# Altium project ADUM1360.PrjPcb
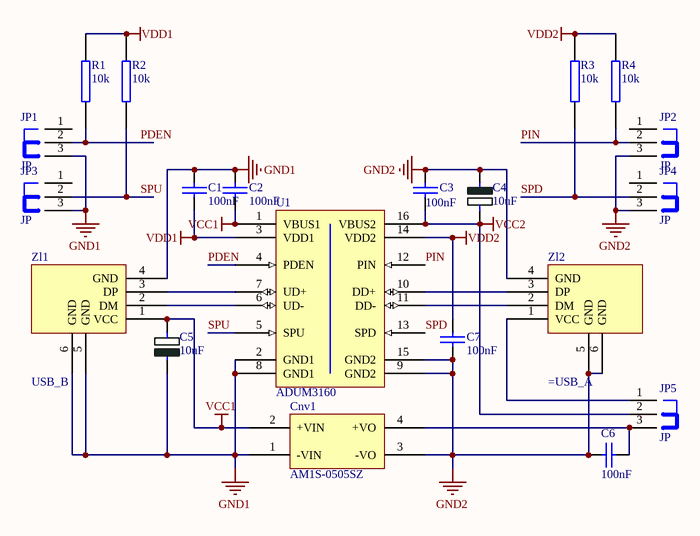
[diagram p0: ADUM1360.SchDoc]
1 sheet, 20 parts. Net scope: global (net labels, ports and power ports of the same name join across sheets).
Board file: adum1360.PcbDoc

## Sheet ADUM1360.SchDoc
size A4

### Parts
C1  100nF  [0805]
C2  100nF  [0805]
C3  100nF  [0805]
C4  10uF  [CE_SMD_W]
C5  10uF  [CE_SMD_W]
C6  100nF  [0805]
C7  100nF  [0805]
Cnv1  AM1S-0505SZ  [SIP4_AM1S]
JP1  JP  [sip-3]
JP2  JP  [sip-3]
JP3  JP  [sip-3]
JP4  JP  [sip-3]
JP5  JP  [sip-3]
R1  10k  [0805]
R2  10k  [0805]
R3  10k  [0805]
R4  10k  [0805]
U1  ADUM3160  [SOL-16]
Zl1  USB_B  [USB_B]
Zl2  (no value)  [USB_A]

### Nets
GND1: C1.1 C2.1 C5.2(MINUS) Cnv1.1(-VIN) JP1.3 JP3.3 U1.2(GND1) U1.8(GND1) Zl1.4(GND) Zl1.5(GND) Zl1.6(GND)
GND2: C3.1 C4.2(MINUS) C6.1 C7.2 Cnv1.3(-VO) JP2.3 JP4.3 U1.9(GND2) U1.15(GND2) Zl2.4(GND) Zl2.5(GND) Zl2.6(GND)
VCC1: C2.2 C5.1(PLUS) Cnv1.2(+VIN) U1.1(VBUS1) Zl1.1(VCC)
VCC2: C3.2 C4.1(PLUS) JP5.2 U1.16(VBUS2)
VDD1: C1.2 R1.2 R2.2 U1.3(VDD1)
VDD2: C7.1 R3.2 R4.2 U1.14(VDD2)
PDEN: JP1.2 R1.1 U1.4(PDEN)
PIN: JP2.2 R4.1 U1.12(PIN)
SPD: JP4.2 R3.1 U1.13(SPD)
SPU: JP3.2 R2.1 U1.5(SPU)
NetC6_2: C6.2 Cnv1.4(+VO) JP5.3
NetJP5_1: JP5.1 Zl2.1(VCC)
NetU1_6: U1.6(UD-) Zl1.2(DM)
NetU1_7: U1.7(UD+) Zl1.3(DP)
NetU1_10: U1.10(DD+) Zl2.3(DP)
NetU1_11: U1.11(DD-) Zl2.2(DM)

Not connected (* = marked no-connect by the designer): JP1 1; JP2 1; JP3 1; JP4 1

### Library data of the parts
C1 C3 C7 = CAP: Capacitor
C2 C6 = Cap: Capacitor
C4 C5 = CP: Capacitor
JP1-JP5 = JP: Jumper
R1-R4 = RES2
Zl1 Zl2 = USB_A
